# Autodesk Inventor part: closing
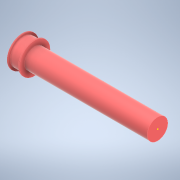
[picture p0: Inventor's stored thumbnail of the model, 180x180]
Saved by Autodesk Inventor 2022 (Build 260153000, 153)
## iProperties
Created: 2021-06
Part Number: closing
Material: PC/ABS Plastic
Document SubType Name: Modeling
Designer: Chimms
Density: 0.357273 g/cm^3
Appearance: Smooth - White
Author: Chimms
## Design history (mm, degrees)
sketch "Sketch1"
  geometry: C1 r 6.5 at (0, 0); C2 r 7.5 at (0, 0)
  constraints: 2 centre point, 1 coincident
  dimensions: "d1" = 13 diameter of C1; "d3" = 15 diameter of C2
extrude "Extrusion1" new body sketch "Sketch1" distance "d4" = 5; taper "d5" = 0 deg
sketch "Sketch2"
  geometry: C1 r 7.5 at (0, 0); 1 further point
  constraints: 1 centre point, 1 coincident
  dimensions: "d6" = 15 diameter of C1
sketch "Sketch3"
  geometry: C1 r 7.5 at (0, 0); 1 further point
  constraints: 1 centre point, 1 coincident
  dimensions: "d7" = 15 diameter of C1
extrude "Extrusion2" join sketch "Sketch3" distance "d8" = 0.5; taper "d9" = 0 deg
extrude "Extrusion3" join sketch "Sketch2" distance "d10" = 0.5; taper "d11" = 0 deg
sketch "Sketch4"
  geometry: C1 r 5 at (0, 0); 1 further point
  constraints: 1 centre point, 1 coincident
  dimensions: "d12" = 10 diameter of C1
extrude "Extrusion4" join sketch "Sketch4" distance "d13" = 120; taper "d14" = 0 deg
fillet "Fillet1" dims "d15" = 1
sketch "Sketch5"
  geometry: C1 r 5 at (0, 0); 1 further point
  constraints: 1 centre point, 1 coincident
extrude "Extrusion5" cut sketch "Sketch5" distance "d16" = 40; taper "d17" = 0 deg
fillet "Fillet2" dims "d18" = 0.8
sketch "Sketch6"
  geometry: C1 r 5 at (0, 0); 1 further point
  constraints: 1 centre point, 1 coincident
extrude "Extrusion6" cut sketch "Sketch6" distance "d19" = 20; taper "d20" = 0 deg
sketch "Sketch7"
  geometry: C1 r 5 at (0, 0); 1 further point
  constraints: 1 centre point, 1 coincident
  dimensions: "d21" = 10 diameter of C1
extrude "Extrusion7" cut sketch "Sketch7" distance "d22" = 30; taper "d23" = 0 deg
sketch "Sketch8"
  geometry: C1 r 5 at (0, 0); 1 further point
  constraints: 1 centre point, 1 coincident
  dimensions: "d24" = 10 diameter of C1
extrude "Extrusion8" join sketch "Sketch8" distance "d25" = 30; taper "d26" = 0 deg
sketch "Sketch9"
  geometry: 1 further point
sketch "Sketch10"
  geometry: C1 r 2 at (0, 0); 1 further point
  constraints: 1 centre point, 1 coincident
  dimensions: "d27" = 4 diameter of C1
extrude "Extrusion9" cut sketch "Sketch10" distance "d28" = 4.5; taper "d29" = 0 deg
body "Solid1"
